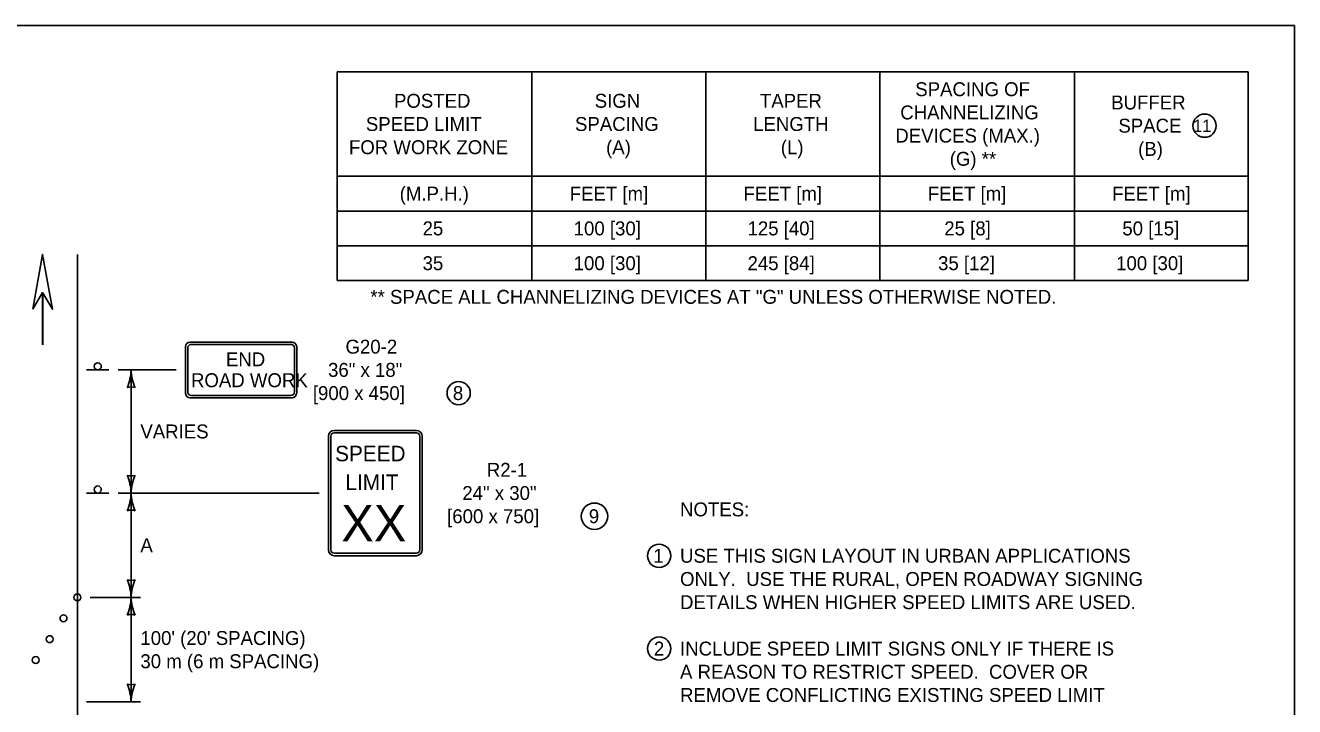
# Model space of a CAD drawing. Extents: x 49991.4 to 50021, y 49987.6 to 50011.4.
# Drawn here: x 50003.14 to 50008.61, y 50008.33 to 50011.26 of the extents above; entities that cross this region are included whole.
import ezdxf

# ---------------------------------------------------------------- set-up
doc = ezdxf.new("R2010")
doc.units = 0
for name, color, linetype in [('Level 1', 7, 'Continuous'), ('Level 2', 7, 'Continuous'), ('Level 3', 7, 'Continuous')]:
    doc.layers.add(name, color=color, linetype=linetype)

msp = doc.modelspace()

# ---------------------------------------------------------------- linework, layer by layer
at = {"layer": 'Level 1'}
for p, q in [((50003.3635, 50008.3655), (50003.3635, 50010.2756)), ((50003.2135, 50009.8855), (50003.2135, 50010.1114)), ((50003.2139, 50009.8855), (50003.2139, 50010.1114)), ((50003.8295, 50009.678), (50003.8295, 50009.878)), ((50003.8395, 50009.683), (50003.8395, 50009.873)), ((50004.2895, 50009.898), (50003.8495, 50009.898)), ((50004.2845, 50009.888), (50003.8545, 50009.888)), ((50004.2995, 50009.873), (50004.2995, 50009.683)), ((50004.3095, 50009.878), (50004.3095, 50009.678)), ((50003.4995, 50009.778), (50003.4035, 50009.778)), ((50004.2894, 50009.658), (50003.8494, 50009.658)), ((50004.2845, 50009.668), (50003.8545, 50009.668)), ((50004.4461, 50009.0025), (50004.4461, 50009.492)), ((50004.4567, 50009.0025), (50004.4567, 50009.492)), ((50004.4714, 50009.5173), (50004.8259, 50009.5173)), ((50004.4714, 50009.5067), (50004.8259, 50009.5067)), ((50004.6487, 50009.5173), (50004.6487, 50009.5173)), ((50004.8406, 50009.492), (50004.8406, 50009.0025)), ((50004.8512, 50009.492), (50004.8512, 50009.0025)), ((50003.4995, 50009.2472), (50003.4035, 50009.2472)), ((50004.8259, 50008.9877), (50004.4714, 50008.9877)), ((50004.8259, 50008.9772), (50004.4714, 50008.9772)), ((50003.3635, 50006.2425), (50003.3635, 50008.3654))]:
    msp.add_line(p, q, dxfattribs=at)
for points in [[(50008.6146, 50011.2628), (50000.3356, 50011.2628), (50000.3356, 50000.0624), (50008.6146, 50000.0624)], [(50003.1719, 50010.0391), (50003.2135, 50010.2756), (50003.2555, 50010.0391), (50003.2135, 50010.1113)]]:
    msp.add_lwpolyline(points, close=True, dxfattribs=at)
for centre, radius in [((50003.4514, 50009.7932), 0.0152), ((50003.4514, 50009.2624), 0.0152), ((50003.3637, 50008.7973), 0.015), ((50003.3037, 50008.7073), 0.015), ((50003.2437, 50008.6173), 0.015), ((50003.1838, 50008.5273), 0.015)]:
    msp.add_circle(centre, radius, dxfattribs=at)
for centre, radius, start, end in [((50003.8495, 50009.878), 0.02, 90, 180), ((50003.8545, 50009.873), 0.015, 90, 180), ((50004.2845, 50009.873), 0.015, 360, 90), ((50004.2895, 50009.878), 0.02, 360, 90), ((50003.8494, 50009.678), 0.02, 180, 270), ((50003.8545, 50009.683), 0.015, 180, 270), ((50004.2845, 50009.683), 0.015, 270, 360), ((50004.2894, 50009.678), 0.02, 270, 360), ((50004.4714, 50009.492), 0.0253, 90, 180), ((50004.4714, 50009.492), 0.0148, 90, 180), ((50004.8259, 50009.492), 0.0253, 0, 90), ((50004.8259, 50009.492), 0.0148, 0, 90), ((50004.4714, 50009.0025), 0.0253, 180, 270), ((50004.4714, 50009.0025), 0.0148, 180, 270), ((50004.8259, 50009.0025), 0.0148, 270, 360), ((50004.8259, 50009.0025), 0.0253, 270, 360)]:
    msp.add_arc(centre, radius, start, end, dxfattribs=at)
at = {"layer": 'Level 2'}
for p, q in [((50004.4846, 50011.0628), (50008.4146, 50011.0628)), ((50004.4846, 50011.0628), (50004.4846, 50010.1628)), ((50005.3246, 50011.0628), (50005.3246, 50010.1628)), ((50006.0746, 50011.0628), (50006.0746, 50010.1628)), ((50006.8246, 50011.0628), (50006.8246, 50010.1628)), ((50007.6646, 50011.0628), (50007.6646, 50010.1628)), ((50008.4146, 50011.0628), (50008.4146, 50010.1628)), ((50004.4846, 50010.6128), (50008.4146, 50010.6128)), ((50004.4846, 50010.4628), (50008.4146, 50010.4628)), ((50004.4846, 50010.3128), (50008.4146, 50010.3128)), ((50004.4846, 50010.1628), (50008.4146, 50010.1628))]:
    msp.add_line(p, q, dxfattribs=at)
for centre, radius in [((50008.2262, 50010.8305), 0.0501), ((50005.0083, 50009.678), 0.0501), ((50005.5943, 50009.1472), 0.0569), ((50005.8732, 50008.9767), 0.0501), ((50005.8734, 50008.5767), 0.0501)]:
    msp.add_circle(centre, radius, dxfattribs=at)
at = {"layer": 'Level 3'}
for p, q in [((50003.5395, 50009.778), (50003.5953, 50009.778)), ((50003.5953, 50009.2472), (50003.5953, 50009.778)), ((50003.5953, 50009.778), (50003.7895, 50009.778)), ((50004.2941, 50009.2472), (50003.5395, 50009.2472)), ((50003.5953, 50008.7972), (50003.5953, 50009.2472)), ((50004.2941, 50009.2472), (50004.4061, 50009.2472)), ((50005.9574, 50009.0066), (50005.9574, 50009.0066)), ((50003.4187, 50008.7972), (50003.6353, 50008.7972)), ((50003.5953, 50008.7972), (50003.5953, 50008.3472)), ((50003.4035, 50008.3472), (50003.6353, 50008.3472))]:
    msp.add_line(p, q, dxfattribs=at)
for centre, radius, start, end in [((50003.3731, 50009.7872), 0.2223, 337.456, 357.6395), ((50003.828, 50009.7895), 0.233, 182.8273, 202.0772), ((50003.5953, 50009.6498), 0.0548, 72.1388, 107.8612), ((50003.5953, 50009.3755), 0.0548, 252.1388, 287.8612), ((50003.3625, 50009.2357), 0.233, 2.8273, 22.0772), ((50003.8174, 50009.2381), 0.2223, 157.456, 177.6395), ((50003.3731, 50009.2564), 0.2223, 337.456, 357.6395), ((50003.828, 50009.2587), 0.233, 182.8273, 202.0772), ((50003.5953, 50009.119), 0.0548, 72.1388, 107.8612), ((50003.5953, 50008.9255), 0.0548, 252.1388, 287.8612), ((50003.3625, 50008.7857), 0.233, 2.8273, 22.0772), ((50003.8174, 50008.7881), 0.2223, 157.456, 177.6395), ((50003.3731, 50008.8064), 0.2223, 337.456, 357.6395), ((50003.828, 50008.8087), 0.233, 182.8273, 202.0772), ((50003.5953, 50008.669), 0.0548, 72.1388, 107.8612), ((50003.5953, 50008.4755), 0.0548, 252.1388, 287.8612), ((50003.3625, 50008.3357), 0.233, 2.8273, 22.0772), ((50003.8174, 50008.3381), 0.2223, 157.456, 177.6395)]:
    msp.add_arc(centre, radius, start, end, dxfattribs=at)

# ---------------------------------------------------------------- texts
at = {"layer": 'Level 1'}
for s, p in [('END', (50004.0043, 50009.7934)), ('ROAD WORK', (50003.8536, 50009.7034))]:
    msp.add_text(s, height=0.06, rotation=360, dxfattribs=at).set_placement(p)
for s, height, p in [('SPEED', 0.06695, (50004.4756, 50009.384)), ('LIMIT', 0.06695, (50004.5199, 50009.2603)), ('XX', 0.15772, (50004.5016, 50009.0383))]:
    msp.add_text(s, height=height, dxfattribs=at).set_placement(p)
at = {"layer": 'Level 2'}
for s, height, p in [('SPACING OF', 0.06, (50006.9781, 50010.9578)), ('POSTED', 0.06, (50004.7293, 50010.9078)), ('SIGN', 0.06, (50005.5953, 50010.9078)), ('TAPER', 0.06, (50006.3079, 50010.9078)), ('CHANNELIZING', 0.06, (50006.9134, 50010.8578)), ('BUFFER', 0.06, (50007.8235, 50010.9005)), ('SPEED LIMIT', 0.06, (50004.608, 50010.8078)), ('SPACING', 0.06, (50005.5102, 50010.8078)), ('LENGTH', 0.06, (50006.2787, 50010.8078)), ('SPACE', 0.06, (50007.8543, 50010.8005)), ('11', 0.05304, (50008.1766, 50010.8039)), ('DEVICES (MAX.)', 0.06, (50006.892, 50010.7578)), ('FOR WORK ZONE', 0.06, (50004.535, 50010.7078)), ('(A)', 0.06, (50005.6443, 50010.7078)), ('(L)', 0.06, (50006.398, 50010.7078)), ('(B)', 0.06, (50007.9395, 50010.7005)), ('(G) **', 0.06, (50007.1267, 50010.6578)), ('(M.P.H.)', 0.06, (50004.7539, 50010.5078)), ('FEET [m]', 0.06, (50005.4873, 50010.5078)), ('FEET [m]', 0.06, (50006.2373, 50010.5078)), ('FEET [m]', 0.06, (50007.0323, 50010.5078)), ('FEET [m]', 0.06, (50007.8273, 50010.5078)), ('25', 0.06, (50004.8528, 50010.3578)), ('100 [30]', 0.06, (50005.5045, 50010.3578)), ('125 [40]', 0.06, (50006.2545, 50010.3578)), ('25 [8]', 0.06, (50007.1033, 50010.3578)), ('50 [15]', 0.06, (50007.8714, 50010.3578)), ('35', 0.06, (50004.8528, 50010.2078)), ('100 [30]', 0.06, (50005.5045, 50010.2078)), ('245 [84]', 0.06, (50006.2545, 50010.2078)), ('35 [12]', 0.06, (50007.0764, 50010.2078)), ('100 [30]', 0.06, (50007.8445, 50010.2078)), ('** SPACE ALL CHANNELIZING DEVICES AT "G" UNLESS OTHERWISE NOTED.', 0.06, (50004.6274, 50010.0628)), ('G20-2', 0.06, (50004.5201, 50009.848)), ('36" x 18"', 0.06, (50004.4449, 50009.748)), ('[900 x 450]', 0.06, (50004.3793, 50009.648)), ('8', 0.06, (50004.9833, 50009.648)), ('VARIES', 0.06, (50003.6353, 50009.4826)), ('R2-1', 0.06, (50005.1298, 50009.3172)), ('24" x 30"', 0.06, (50005.0242, 50009.2172)), ('[600 x 750]', 0.06, (50004.9586, 50009.1172)), ('9', 0.06, (50005.5698, 50009.1172)), ('NOTES:', 0.06, (50005.9633, 50009.1467)), ('1', 0.06, (50005.8478, 50008.9466)), ('USE THIS SIGN LAYOUT IN URBAN APPLICATIONS', 0.06, (50005.9633, 50008.9467)), ('ONLY.  USE THE RURAL, OPEN ROADWAY SIGNING ', 0.06, (50005.9633, 50008.8467)), ('DETAILS WHEN HIGHER SPEED LIMITS ARE USED.', 0.06, (50005.9633, 50008.7467)), ("100' (20' SPACING)", 0.06, (50003.6353, 50008.5922)), ('2', 0.06, (50005.8505, 50008.5467)), ('INCLUDE SPEED LIMIT SIGNS ONLY IF THERE IS', 0.06, (50005.9633, 50008.5467)), ('30 m (6 m SPACING)', 0.06, (50003.6353, 50008.4922)), ('A REASON TO RESTRICT SPEED.  COVER OR ', 0.06, (50005.9633, 50008.4467)), ('REMOVE CONFLICTING EXISTING SPEED LIMIT ', 0.06, (50005.9633, 50008.3467))]:
    msp.add_text(s, height=height, dxfattribs=at).set_placement(p)
msp.add_text('A', height=0.06, rotation=360, dxfattribs=at).set_placement((50003.6353, 50008.9922))

doc.saveas('drawing.dxf')
